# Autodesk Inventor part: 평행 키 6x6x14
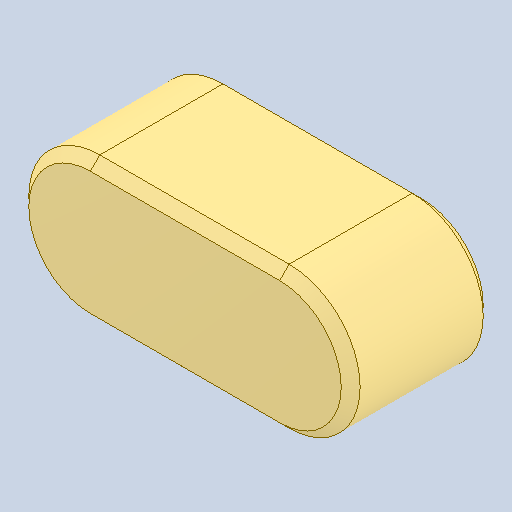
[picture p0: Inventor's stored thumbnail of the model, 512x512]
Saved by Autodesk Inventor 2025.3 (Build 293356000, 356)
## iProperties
Created: 2025-09
Part Number: 평행 키 6x6x14
Material: 강철, 연강
Description: 키 및 해당 키홈
Document SubType Name: Modeling
Designer: PC-15
Density: 7.85 g/cm^3
Appearance: 기본값
Author: jhkim
Sending System: Autodesk Inventor 2026
Preprocessor: ST-DEVELOPER v20.1
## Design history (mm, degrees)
feature "Solid1"
node "솔리드1"
